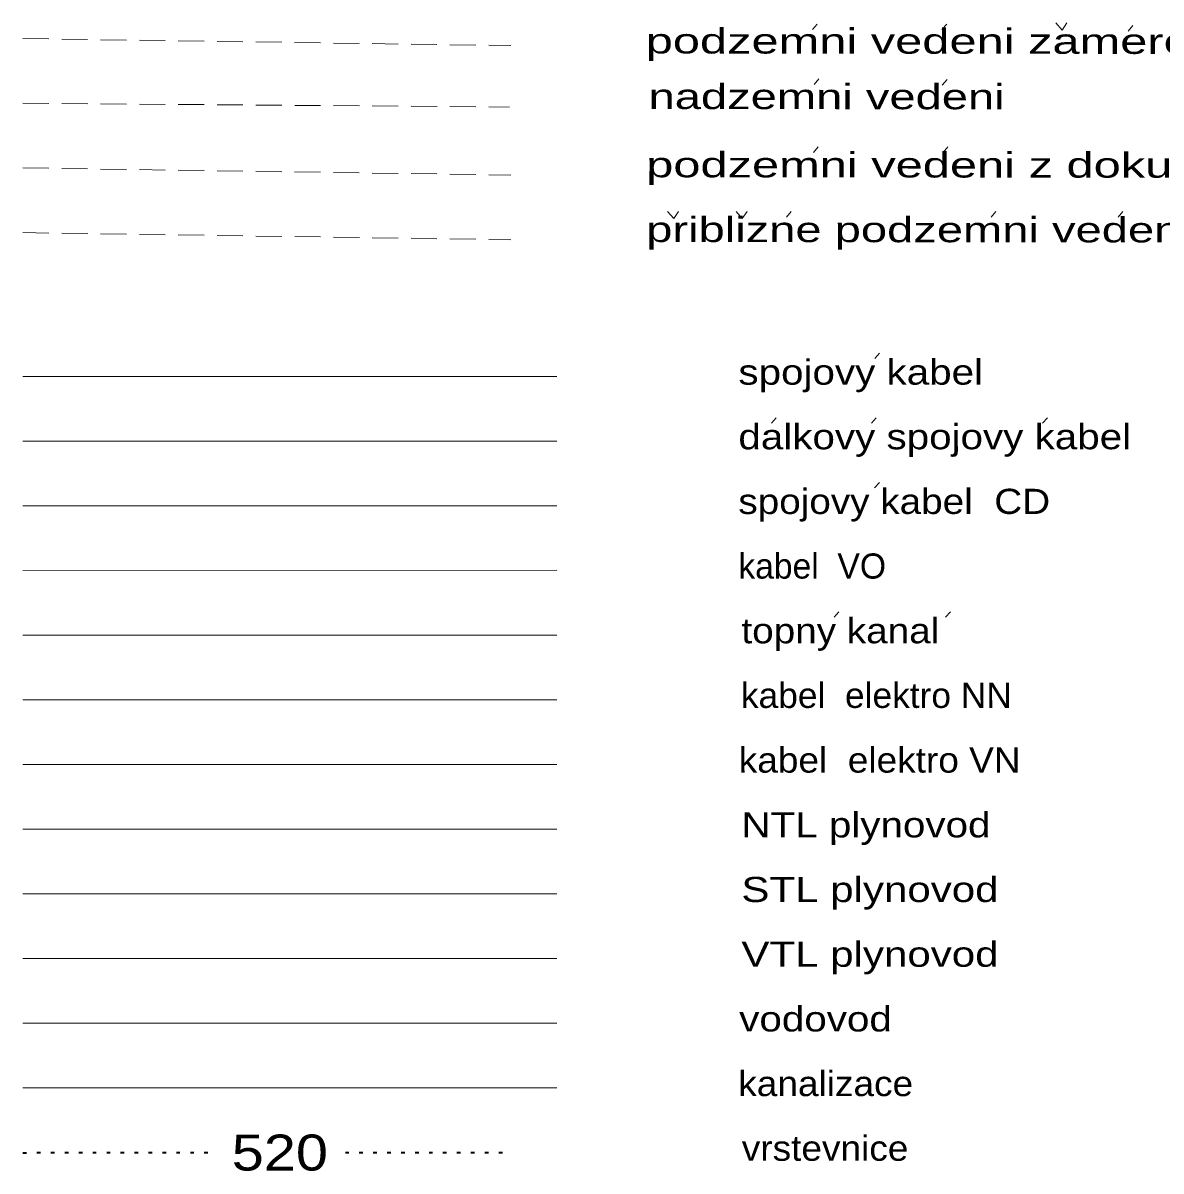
# Model space of a CAD drawing. Extents: x -670514 to -669423, y -1130798 to -1130123.
# Drawn here: x -670332.91 to -670301.24, y -1130264.09 to -1130232.15 of the extents above; entities that cross this region are included whole.
import ezdxf
from ezdxf.enums import TextEntityAlignment as Align

# ---------------------------------------------------------------- set-up
doc = ezdxf.new("R2010")
doc.units = 0
doc.header["$LTSCALE"] = 0.24
doc.linetypes.add('DOTTED', pattern=[1.5, 0.3, -1.2])
doc.linetypes.add('MEDIUM_DASHED', pattern=[4.5, 3, -1.5])
doc.layers.add('61', color=7, linetype='Continuous', lineweight=13)

msp = doc.modelspace()

# ---------------------------------------------------------------- linework, layer by layer
at = {"layer": '61'}
for p, q in [((-670310.941, -1130232.331), (-670310.808, -1130232.176)), ((-670307.336, -1130232.331), (-670307.203, -1130232.176)), ((-670302.157, -1130232.374), (-670302.025, -1130232.22)), ((-670310.895, -1130233.856), (-670310.763, -1130233.702)), ((-670307.326, -1130233.878), (-670307.193, -1130233.724)), ((-670310.908, -1130235.748), (-670310.776, -1130235.594)), ((-670307.303, -1130235.748), (-670307.171, -1130235.594)), ((-670311.665, -1130237.549), (-670311.533, -1130237.395)), ((-670305.97, -1130237.548), (-670305.838, -1130237.394)), ((-670302.433, -1130237.548), (-670302.301, -1130237.395)), ((-670309.207, -1130241.485), (-670309.076, -1130241.331)), ((-670332.904, -1130241.982), (-670318.052, -1130241.983)), ((-670312.082, -1130243.285), (-670311.951, -1130243.131)), ((-670309.3, -1130243.285), (-670309.168, -1130243.131)), ((-670304.534, -1130243.286), (-670304.403, -1130243.132)), ((-670332.905, -1130243.78), (-670318.053, -1130243.781)), ((-670309.208, -1130245.085), (-670309.077, -1130244.931)), ((-670332.905, -1130245.58), (-670318.054, -1130245.582)), ((-670332.904, -1130247.38), (-670318.053, -1130247.377)), ((-670310.332, -1130248.682), (-670310.201, -1130248.528)), ((-670307.232, -1130248.682), (-670307.101, -1130248.528)), ((-670332.905, -1130249.18), (-670318.051, -1130249.18)), ((-670332.905, -1130250.98), (-670318.053, -1130250.977)), ((-670332.904, -1130252.78), (-670318.051, -1130252.777)), ((-670332.905, -1130254.581), (-670318.051, -1130254.58)), ((-670332.905, -1130256.38), (-670318.051, -1130256.379)), ((-670332.904, -1130258.18), (-670318.051, -1130258.18)), ((-670332.905, -1130259.98), (-670318.052, -1130259.978)), ((-670332.905, -1130261.78), (-670318.053, -1130261.778))]:
    msp.add_line(p, q, dxfattribs=at)
at = {"layer": '61', "linetype": 'MEDIUM_DASHED'}
for p, q in [((-670332.905, -1130232.581), (-670319.332, -1130232.778)), ((-670332.904, -1130234.381), (-670319.371, -1130234.486)), ((-670332.905, -1130236.181), (-670319.331, -1130236.379)), ((-670332.904, -1130237.982), (-670319.33, -1130238.179))]:
    msp.add_line(p, q, dxfattribs=at)
at = {"layer": '61', "linetype": 'DOTTED', "lineweight": 35}
for p, q in [((-670332.904, -1130263.581), (-670327.581, -1130263.579)), ((-670323.935, -1130263.577), (-670319.405, -1130263.575))]:
    msp.add_line(p, q, dxfattribs=at)
at = {"layer": '61'}
for points in [[(-670304.168, -1130232.147), (-670303.994, -1130232.346), (-670303.862, -1130232.147)], [(-670314.971, -1130237.394), (-670314.796, -1130237.592), (-670314.664, -1130237.393)], [(-670313.064, -1130237.393), (-670312.89, -1130237.591), (-670312.758, -1130237.392)]]:
    msp.add_lwpolyline(points, dxfattribs=at)

# ---------------------------------------------------------------- texts
for s, rotation, width, p in [('podzemni vedeni zamerene geodeticky', 359.949, 1.45, (-670315.578, -1130232.995)), ('nadzemni vedeni', 359.949, 1.4, (-670315.499, -1130234.541)), ('podzemni vedeni z dokumentace', 359.949, 1.45, (-670315.564, -1130236.44)), ('priblizne podzemni vedeni', 359.949, 1.4, (-670315.564, -1130238.241)), ('spojovy kabel', 0.01, 1.2, (-670312.998, -1130242.212)), ('dalkovy spojovy kabel', 0.01, 1.2, (-670312.999, -1130244.01)), ('spojovy kabel  CD', 0.01, 1.15, (-670313, -1130245.81)), ('topny kanal', 0.01, 1.15, (-670312.915, -1130249.408)), ('kabel  elektro NN', 0.01, 1.05, (-670312.929, -1130251.207)), ('kabel  elektro VN', 0.01, 1.1, (-670312.989, -1130253.007)), ('NTL plynovod', 0.01, 1.2, (-670312.915, -1130254.809)), ('STL plynovod', 0.01, 1.25, (-670312.915, -1130256.608)), ('VTL plynovod', 0.01, 1.25, (-670312.915, -1130258.409)), ('vodovod', 0.01, 1.2, (-670312.976, -1130260.209)), ('kanalizace', 0.01, 1.1, (-670313.002, -1130262.008)), ('vrstevnice', 0.01, 1.1, (-670312.904, -1130263.807))]:
    msp.add_text(s, height=0.7, rotation=rotation, dxfattribs=dict(at, width=width)).set_placement(p)
msp.add_text('kabel  VO', height=0.7, rotation=0.01, dxfattribs=at).set_placement((-670313.001, -1130247.608))
at = {"layer": '61', "width": 1.2}
msp.add_text('520', height=1, rotation=0.021, dxfattribs=at).set_placement((-670325.7572, -1130264.0775), align=Align.CENTER)

doc.saveas('drawing.dxf')
